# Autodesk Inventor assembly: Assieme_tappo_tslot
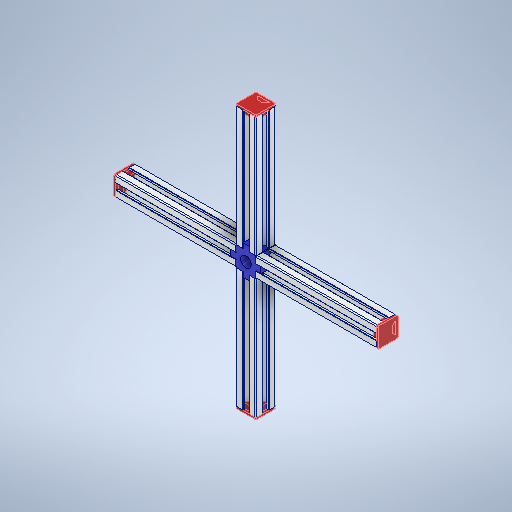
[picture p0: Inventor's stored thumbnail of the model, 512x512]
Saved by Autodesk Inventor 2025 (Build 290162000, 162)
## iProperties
Created: 2026-02
Part Number: Assieme_tappo_tslot
Document SubType Name: Assembly
Designer: R5800u
Author: R5800u
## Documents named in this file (4)
- C:\Users\Ryzen5700u\Desktop\antropomorfo_nema5\Assieme_tappo_tslot.iam
- C:\Users\Ryzen5700u\Desktop\antropomorfo_nema5\tslot-20x20-3.ipt
- C:\Users\Ryzen5700u\Desktop\antropomorfo_nema5\tappo_01.ipt
- C:\Users\Ryzen5700u\Desktop\antropomorfo_nema5\tappo6.ipt
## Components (9 placed, 3 different names)
1. tappo6:1 — Coincidente:6, Allineato:10, Allineato:11
2. tslot-20x20-3:6 — Coincidente:6, Allineato:10, Allineato:11
3. tslot-20x20-3:7
4. tslot-20x20-3:8 — Coincidente:7, Allineato:12, Allineato:13
5. tslot-20x20-3:9
6. tappo_01:1 — Coincidente:7, Allineato:12, Allineato:13
7. tappo_01:2
8. tappo_01:3
9. tappo_01:4
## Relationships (6: Flush 4, Mate 2)
- Coincidente:6 [Mate]: tappo6:1 ↔ tslot-20x20-3:6
- Allineato:10 [Flush]: tappo6:1 ↔ tslot-20x20-3:6
- Allineato:11 [Flush]: tappo6:1 ↔ tslot-20x20-3:6
- Coincidente:7 [Mate]: tslot-20x20-3:8 ↔ tappo_01:1
- Allineato:12 [Flush]: tslot-20x20-3:8 ↔ tappo_01:1
- Allineato:13 [Flush]: tslot-20x20-3:8 ↔ tappo_01:1
